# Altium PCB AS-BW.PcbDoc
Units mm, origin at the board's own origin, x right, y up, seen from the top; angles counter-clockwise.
Board outline 39.02 x 30.02 mm, 2 copper layers (Top Layer, Bottom Layer); 17 components, 20 nets, 101 pads, 184 vias.
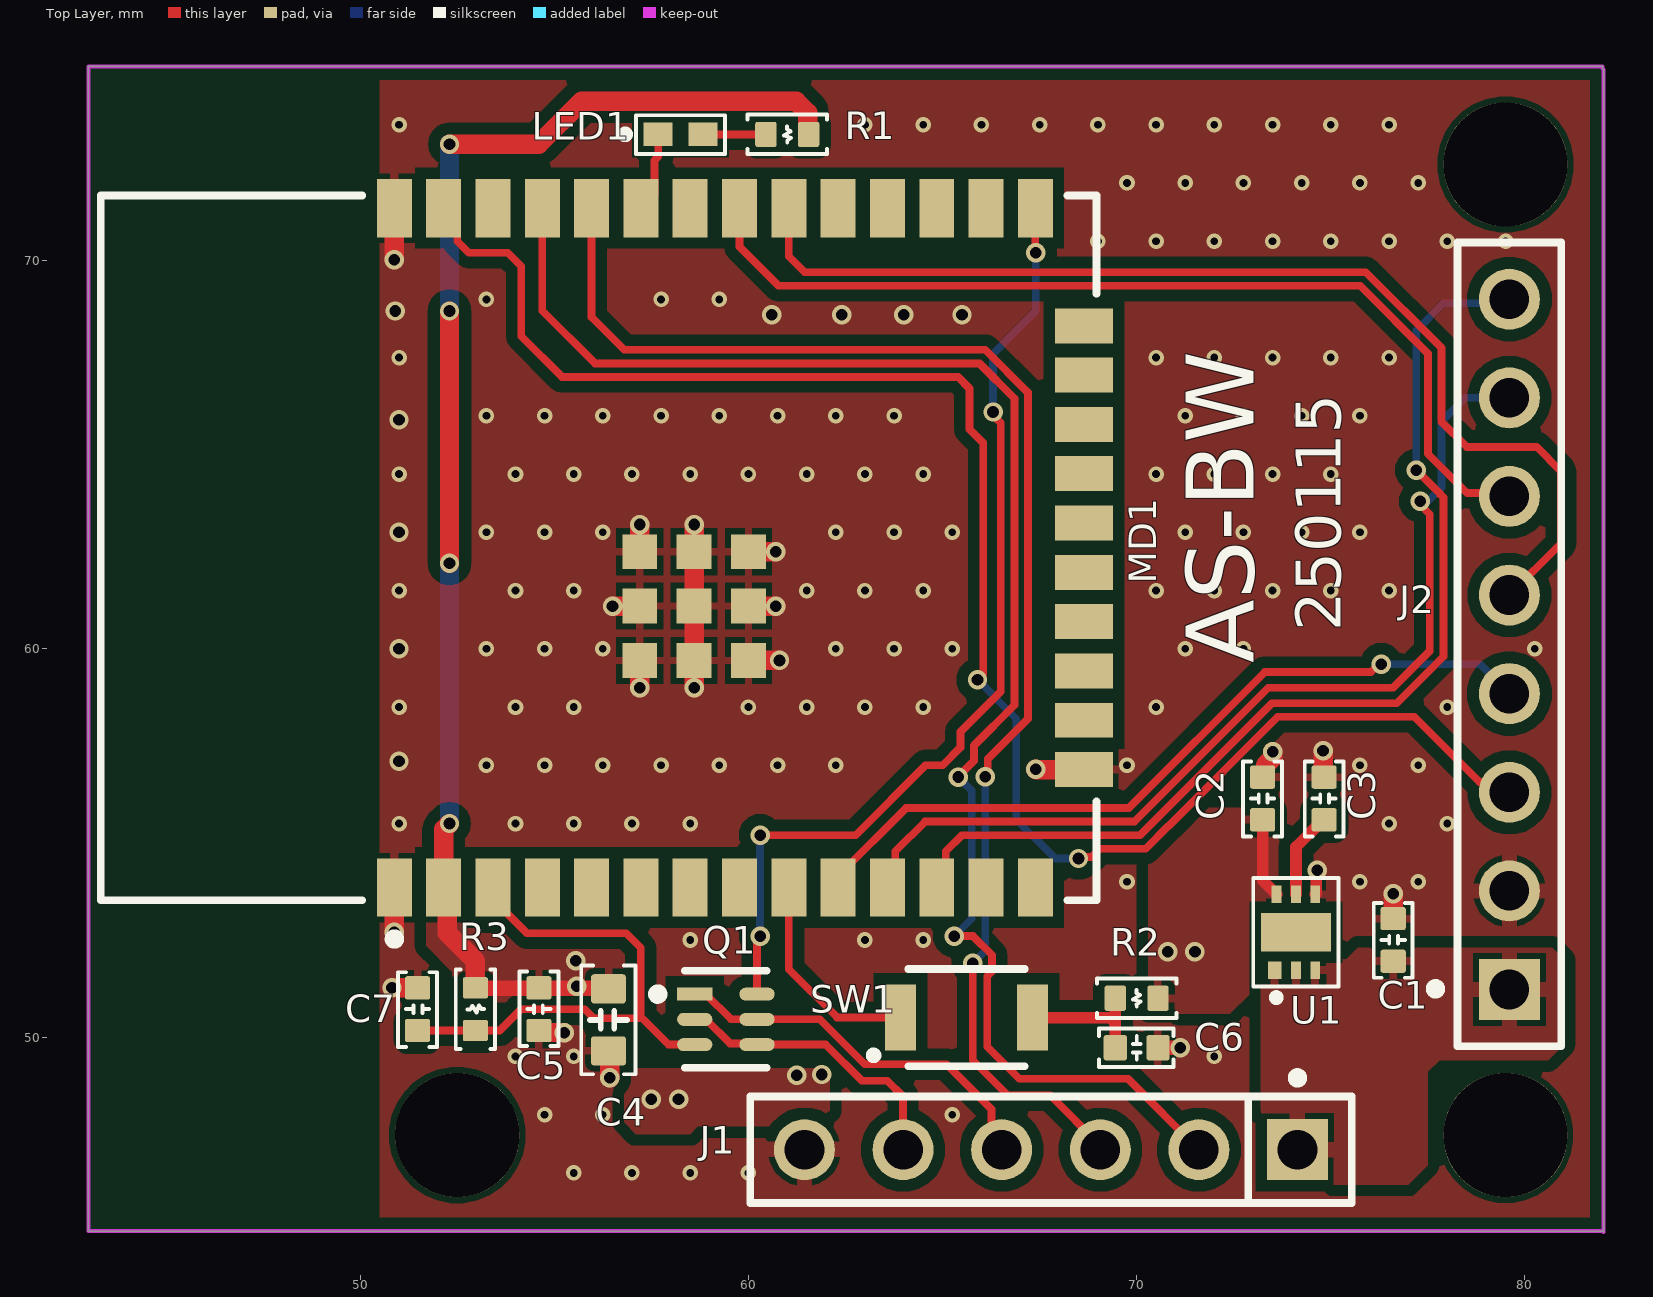
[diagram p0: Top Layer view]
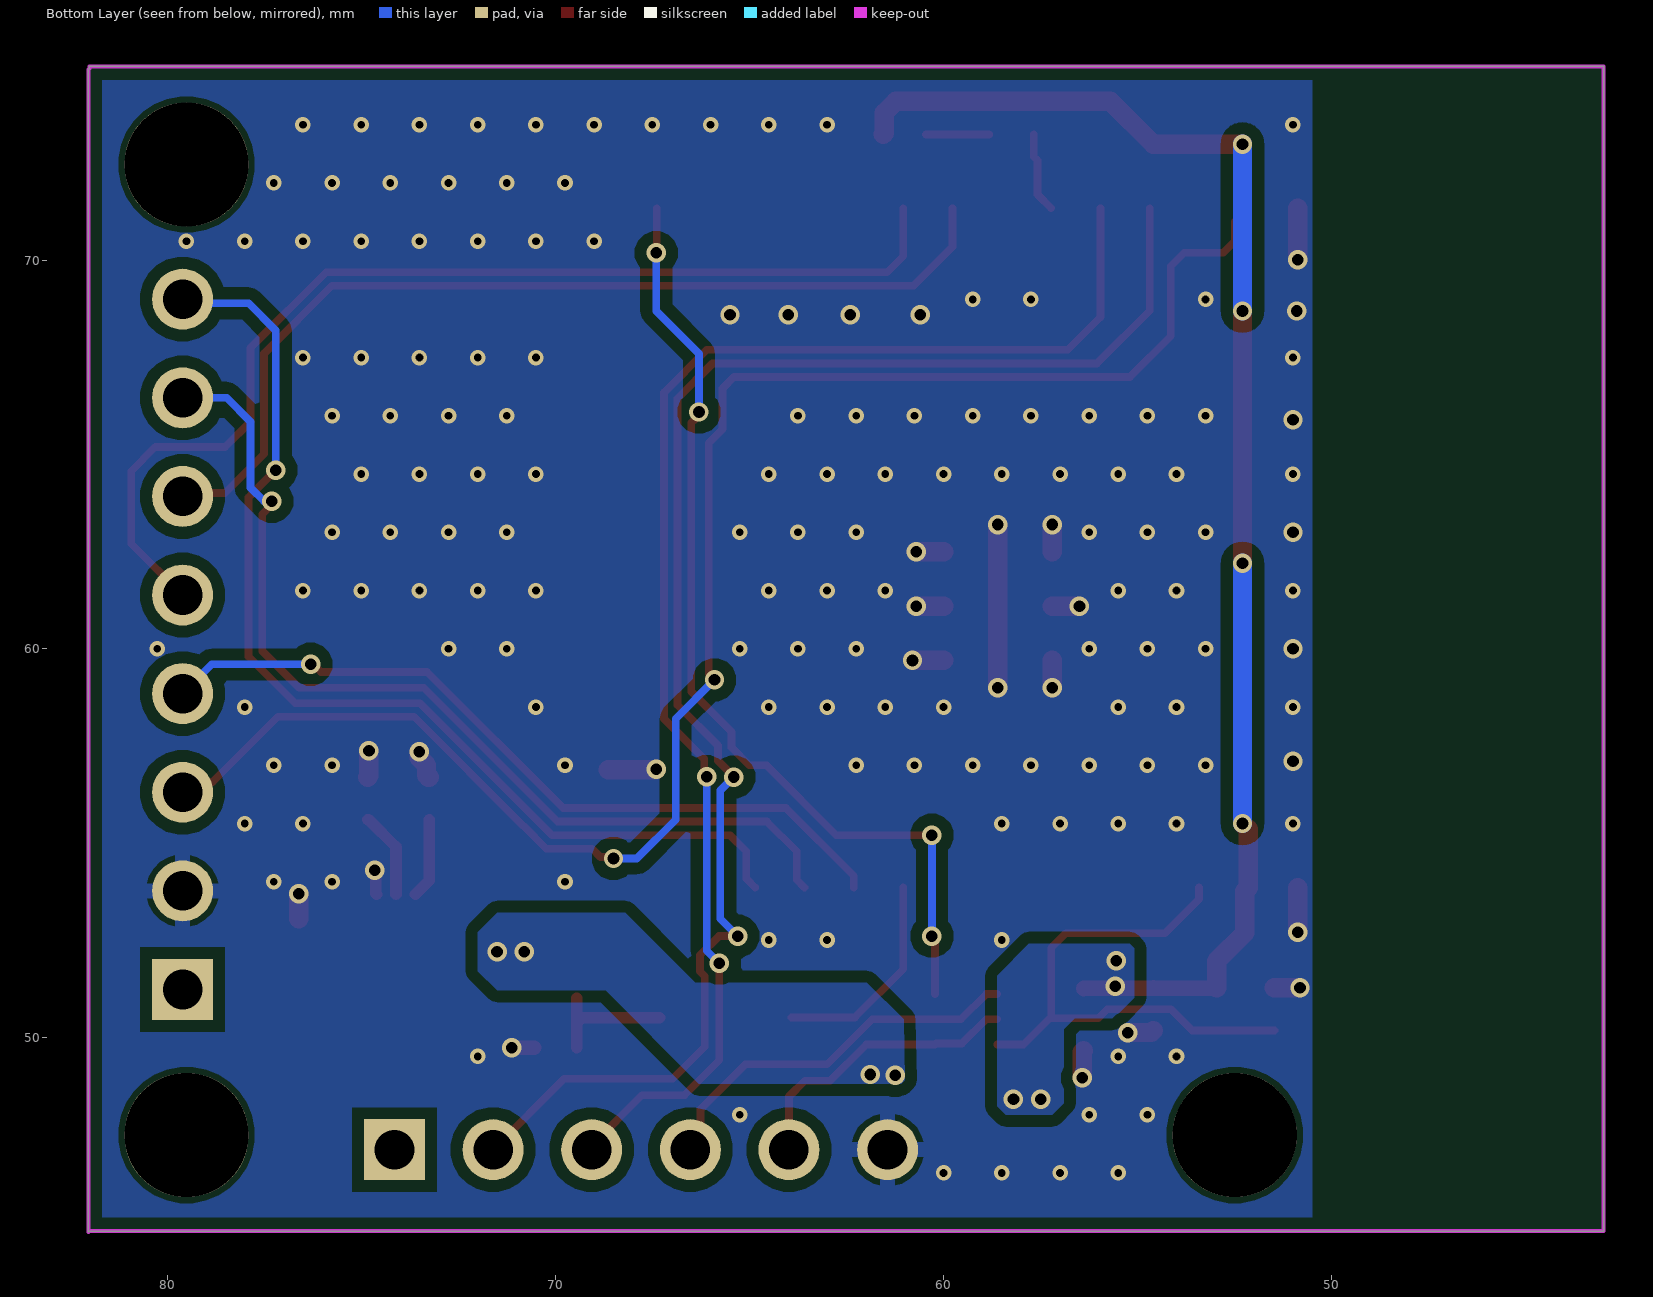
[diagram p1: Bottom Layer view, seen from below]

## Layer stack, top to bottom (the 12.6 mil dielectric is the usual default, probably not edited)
Top Solder: solder mask 0.0102, Solder Resist, Dk 3.5
Top Layer: signal copper 0.0356
Dielectric 1: dielectric 0.32, FR-4, Dk 4.8
Bottom Layer: signal copper 0.0356
Bottom Solder: solder mask 0.0102, Solder Resist, Dk 3.5

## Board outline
43,45 82,45 82.025,44.975 82.025,74.925 82,74.95 82,75 43,75

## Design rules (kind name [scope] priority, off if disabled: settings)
AssemblyTestPointUsage [All] p1 off:
AssemblyTestpoint [All] p1 off: testpointundercomponent=TRUE minsize=1.016 maxsize=2.54 preferedsize=1.524 minholesize=0 maxholesize=1.016 preferedholesize=0.813 testpointgrid=0.025 usegrid=TRUE gridtolerance=0 allowsidetop=TRUE allowsidebottom=TRUE
BoardOutlineClearance BoardOutlineClearance_1 [OnLayer('Layer 2')] p1 off: gap=0.7 ignorepadtopadclearanceinfootprint=FALSE
BoardOutlineClearance [All] p2 off: gap=0.3 ignorepadtopadclearanceinfootprint=FALSE
Clearance [All] p1: gap=0.15 ignorepadtopadclearanceinfootprint=FALSE except(0.3: Arc-Fill Arc-Poly Arc-Region Track-Fill Track-Poly Track-Region SMDPad-Fill SMDPad-Poly SMDPad-Region THPad-Fill THPad-Poly THPad-Region Via-Fill Via-Poly Via-Region Fill-Fill Fill-Poly Fill-Region Poly-Poly Poly-Region Region-Region)
ComponentClearance [All] p1 off: gap=0.254 collisioncheckmode=3 verticalgap=0.254 showdistances=FALSE
DiffPairsRouting [All] p1: maxlimit=0.254 minlimit=0.1 mostfreqgap=0.1 toplayer_minwidth=0.17 toplayer_maxwidth=0.381 toplayer_prefwidth=0.17 bottomlayer_minwidth=0.17 bottomlayer_maxwidth=0.381 bottomlayer_prefwidth=0.17 maxuncoupledlength=12.7
FabricationTestPointUsage [All] p1 off: valid=0 allowmultiple=FALSE
FabricationTestpoint [All] p1 off: side=3 testpointundercomponent=TRUE minsize=1.016 maxsize=2.54 preferedsize=1.524 minholesize=0 maxholesize=1.016 preferedholesize=0.813 testpointgrid=0.025 allowsidetop=TRUE allowsidebottom=TRUE usegrid=TRUE gridtolerance=0
Height [All] p1 off: minheight=0 maxheight=25.4 prefheight=12.7
HoleSize [All] p1 off: absolutevalues=TRUE maxlimit=2.54 minlimit=0.025 maxpercent=80.000 minpercent=20.000
HoleToHoleClearance [All] p1 off: gap=0.254 allowstackedmicrovias=TRUE
LayerPairs [All] p1 off: enforce=TRUE
MinimumSolderMaskSliver [All] p1 off: minsoldermaskwidth=0.254
NetAntennae [All] p1 off: netantennaetolerance=0
PolygonConnect [All] p1: thpad.connectstyle=Relief thpad.reliefconductorwidth=0.4 thpad.reliefentries=4 thpad.polygonreliefangle="90 Angle" thpad.airgapwidth=0.15 smdpad.connectstyle=Relief smdpad.reliefconductorwidth=0.2 smdpad.reliefentries=4 smdpad.polygonreliefangle="90 Angle" smdpad.airgapwidth=0.15 via.connectstyle=Direct via.reliefconductorwidth=0.254 via.reliefentries=4 via.polygonreliefangle="90 Angle" via.airgapwidth=0.254
RoutingVias [All] p1: holewidth=0.711 width=1.27 viastyle="Through Hole" minholewidth=0.711 minwidth=1.27 maxholewidth=0.711 maxwidth=1.27 useviatemplates=TRUE viatemplateguid#1={E85D0309-8685-4B82-8408-C28B0BDDCD2F} viatemplatename#1=v50h30m0mx0
SilkToSilkClearance [All] p1 off: silktosilkclearance=0.254
SilkToSolderMaskClearance [IsPad] p1 off: minsilkscreentomaskgap=0.254 clearancetoexposedcopper=TRUE
SolderMaskExpansion [All] p1: expansion=0.102 istentingtop=FALSE
SupplyNets "Schematic Supply Nets_3" [InNet('GND')] p1: voltage=0.000
SupplyNets "Schematic Supply Nets_2" [InNet('VCC_1V8')] p2: voltage=0.000
SupplyNets "Schematic Supply Nets_1" [InNet('VCC_5V')] p3: voltage=0.000
SupplyNets "Schematic Supply Nets" [InNet('VCC_3V3')] p4: voltage=0.000
Width [All] p1: maxlimit=3 minlimit=0.15 preferedwidth=0.15
16 further rules are at their usual default settings.

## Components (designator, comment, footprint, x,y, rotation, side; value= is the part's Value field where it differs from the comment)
C1 "Cap Semi" "CAP 0402/1005" 76.607,52.502 r270 top value=1uF
C2 "Cap Semi" "CAP 0402/1005" 73.243,56.145 r270 top value=1uF
C3 "Cap Semi" "CAP 0402/1005" 74.828,56.145 r270 top value=1uF
C4 "Cap Semi" "CAP 0603/1608" 56.395,50.443 r90 top value="22uF /1608"
C5 "Cap Semi" "CAP 0402/1005" 54.603,50.718 r90 top value=100nF
C6 "Cap Semi" "CAP 0402/1005" 70,49.725 r180 top value=100nF
C7 "Cap Semi" "CAP 0402/1005" 51.477,50.718 r270 top value=100nF
J1 "22-28-4060" FP-22-28-4060-MFG 67.792,47.098 r180 top
J2 "TSW-108-08-G-S" FP-TSW-108-08-G-S-MFG 79.6,60.115 r90 top locked
LED1 "QBLP595-IB" "LED 0402/1005 GREEN -21" 58.25,73.25 r180 top
MD1 "ESP32-WROOM-32E (4MB)" FP-ESP32-WROOM-32E_4MB-MFG 56.14,62.6 r90 top
Q1 "UMH3NTN" FP-UMT6-IPC_C 59.418,50.456 r0 top
R1 "Resistor 10k +/-1% 0805 125 mW" "RES 0402/1005" 61,73.25 r180 top value=330
R2 "Resistor 10k +/-1% 0805 125 mW" "RES 0402/1005" 70,51 r180 top value=10K
R3 "Resistor 10k +/-1% 0805 125 mW" "RES 0402/1005" 52.967,50.718 r270 top value=10K
SW1 "B3U-1000P" B3U-1000P 65.617,50.5 r180 top
U1 "VRD1833MLX" "LLP-6 / L2.0-W1.8-P0.50-BL-EP" 74.077,52.699 r0 top

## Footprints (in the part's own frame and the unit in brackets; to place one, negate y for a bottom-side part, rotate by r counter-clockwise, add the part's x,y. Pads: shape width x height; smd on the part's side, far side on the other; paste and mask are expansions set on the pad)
B3U-1000P [mm]
  rect 0.8x1.7 smd: 1(1.7,0) 2(-1.7,0)
  silkscreen extent -1.5,-1.25 2.49,1.25, body extent -2,-1.25 2,1.25, height 1.6
"CAP 0402/1005" [mm] "Chip Capacitor, 2-Leads, Body 1.02x0.51mm, IPC Medium Density"
  rrect20% 0.6x0.65 smd: 1(-0.55,0) 2(0.55,0)
  silkscreen extent -0.95,-0.5 0.97,0.5, body extent -0.5,-0.26 0.5,0.26, height 0.52
"CAP 0603/1608" [mm] "Chip Capacitor, 2-Leads, Body 1.60x0.80mm, IPC Medium Density"
  rrect20% 0.75x0.9 smd: 1(-0.8,0) 2(0.8,0)
  silkscreen extent -1.4,-0.7 1.4,0.7, body extent -0.8,-0.41 0.8,0.41, height 0.82
FP-22-28-4060-MFG [mm]
  rect 1.57x1.57 hole 1.02 paste-2539.97 mask+0: 1(-6.35,0)
  round 1.57 hole 1.02 paste-2539.97 mask+0: 2(-3.81,0) 3(-1.27,0) 4(1.27,0) 5(3.81,0) 6(6.35,0)
  silkscreen extent -7.75,-1.97 7.75,1.37, body extent -7.85,-1.47 7.85,1.47, height 0.25
FP-ESP32-WROOM-32E_4MB-MFG [mm]
  rect 1.5x0.9 smd paste+0 mask+0: 1(-8.75,5.26) 2(-8.75,3.99) 3(-8.75,2.72) 4(-8.75,1.45) 5(-8.75,0.18) 6(-8.75,-1.09) 7(-8.75,-2.36) 8(-8.75,-3.63) 9(-8.75,-4.9) 10(-8.75,-6.17) 11(-8.75,-7.44) 12(-8.75,-8.71) 13(-8.75,-9.98) 14(-8.75,-11.25) 25(8.75,-11.25) 26(8.75,-9.98) 27(8.75,-8.71) 28(8.75,-7.44) 29(8.75,-6.17) 30(8.75,-4.9) 31(8.75,-3.63) 32(8.75,-2.36) 33(8.75,-1.09) 34(8.75,0.18) 35(8.75,1.45) 36(8.75,2.72) 37(8.75,3.99) 38(8.75,5.26)
  rect 0.9x1.5 smd paste+0 mask+0: 15(-5.71,-12.5) 16(-4.44,-12.5) 17(-3.17,-12.5) 18(-1.9,-12.5) 19(-0.63,-12.5) 20(0.64,-12.5) 21(1.91,-12.5) 22(3.18,-12.5) 23(4.45,-12.5) 24(5.72,-12.5)
  rect 0.9x0.9 smd paste+0 mask+0: 39(-2.9,-2.46) 39(-2.9,-1.06) 39(-2.9,-3.86) 39(-1.5,-1.06) 39(-1.5,-3.86) 39(-1.5,-2.46) 39(-0.1,-1.06) 39(-0.1,-2.46) 39(-0.1,-3.86)
  silkscreen extent -10.2,-12.83 9.08,12.83, body extent -9.6,-13.35 9.6,12.93, height 0.25
FP-TSW-108-08-G-S-MFG [mm]
  rect 1.57x1.57 hole 1.02 paste-2539.97 mask+0: 1(-8.89,0)
  round 1.57 hole 1.02 paste-2539.97 mask+0: 2(-6.35,0) 3(-3.81,0) 4(-1.27,0) 5(1.27,0) 6(3.81,0) 7(6.35,0) 8(8.89,0)
  silkscreen extent -10.35,-1.34 10.35,2.03, body extent -10.45,-1.44 10.45,1.44, height 0.25
FP-UMT6-IPC_C [mm]
  rect 0.909x0.336 smd paste+0 mask+0: 1(-0.802,0.65)
  rrect100% 0.909x0.336 smd paste+0 mask+0: 2(-0.802,0) 3(-0.802,-0.65) 4(0.802,-0.65) 5(0.802,0) 6(0.802,0.65)
  silkscreen extent -1.88,-1.25 1.05,1.25, body extent -1.36,-1.1 1.36,1.1, height 0.25
"LED 0402/1005 GREEN -21" [mm] "Chip Diode, 2-Leads, Body 1.00x0.50mm, IPC Medium Density"
  rect 0.75x0.6 smd: 1(0.575,0) 2(-0.575,0)
  silkscreen extent -1.14,-0.49 1.47,0.51, body extent -0.5,-0.25 0.5,0.25, height 0.21
"LLP-6 / L2.0-W1.8-P0.50-BL-EP" [mm]
  rect 0.35x0.45 smd paste+0 mask+0.051: 1(-0.525,-0.975)
  rect 0.25x0.45 smd paste+0 mask+0.051: 2(0.025,-0.975) 3(0.525,-0.975) 4(0.525,0.975) 5(0.025,0.975) 6(-0.475,0.975)
  rect 1.8x1 smd paste+0 mask+0.051: 7(0.025,0)
  silkscreen extent -1.07,-1.74 1.12,1.4, body extent -0.9,-1 0.9,1, height 0.6
"RES 0402/1005" [mm] "Chip Resistor, 2-Leads, Body 1.0x0.5mm, IPC Medium Density"
  rrect20% 0.55x0.65 smd: 1(-0.55,0) 2(0.55,0)
  silkscreen extent -1.02,-0.51 1.02,0.51, body extent -0.5,-0.25 0.5,0.25, height 0.35

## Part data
C1 C2 C3 C4 C5 C6 C7: "Capacitor (Semiconductor SIM Model)"
J1: library part CMP-04776-000763-1, "CONN HEADER VERT 6POS 2.54MM", Color=Black, Contact Resistance=20mR, Current Rating=4A, Max Operating Temperature=75°C, Max Voltage Rating (AC)=250V, Max Voltage Rating (DC)=250.25kV, Min Operating Temperature=0°C, Package Quantity=1
J2: library part CMP-02766-000001-1, "CONN HEADER VERT 8POS 2.54MM", Manufacturer=Samtec, Temperature="-55°C to +125°C", Temperature Range High=+125°C, Temperature Range Low=-55°C
LED1: "Chip LED 0402, Blue, 0.02 A, 3.1 to 3.7 V, -40 to 80 degC, 2-Pin SMD, RoHS, Tape and Reel", Case/Package=0402, Colour=Blue
MD1: library part CMP-194065-000026-1, "RX TXRX MOD WIFI TRACE ANT SMD"
Q1: library part CMP-08979-000010-1, "TRANS 2NPN PREBIAS 0.15W UMT6", Case/Package=SOT-363, Collector Base Voltage (VCBO)=50V, Collector-emitter Voltage-Max=300mV, Continuous Collector Current=100mA, Emitter Base Voltage (VEBO)=5V, Max Operating Temperature=150°C, Max Power Dissipation=150mW, Min Operating Temperature=-55°C, Package Quantity=1, Transition Frequency=250MHz
R1 R2 R3: "Chip Resistor, 10 KOhm, +/- 1%, 125 mW, -55 to 155 degC, 0805 (2012 Metric)", Case/Package=0805, Max Operating Temperature=155°C, Min Operating Temperature=-55°C, Power=125mW, Tolerance=1%, Voltage Rating=150V
SW1: "Tactile Switch, SPST-NO, 0.05 A, 12 V, -25 to 70 degC, 2-Pin SMD, RoHS, Tape and Reel", Case/Package=B3U-1000, Contact Current Rating=50mA, IP Rating=IP40, Manufacturer="Omron Electronic Components", Max Contact Resistance=100mohm, Max Operating Temperature=70°C, Max Voltage Rating (DC)=12V, Min Operating Temperature=-25°C, Operating Force=153gf, Package Description="2-Pin Surface Mount Device, Body 3 x 2.5 mm", Package Quantity=3500, Resistance=0.1Ohm

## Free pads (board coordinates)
  round 3.2 hole 3.2: 0(52.5,47.475) 0(79.5,47.475) 0(79.5,72.475)

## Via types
v1: diameter 0.4, hole 0.2, Top Layer to Bottom Layer, tented both sides, 131 vias
v2: diameter 0.5, hole 0.3, Top Layer to Bottom Layer, tented both sides, 53 vias

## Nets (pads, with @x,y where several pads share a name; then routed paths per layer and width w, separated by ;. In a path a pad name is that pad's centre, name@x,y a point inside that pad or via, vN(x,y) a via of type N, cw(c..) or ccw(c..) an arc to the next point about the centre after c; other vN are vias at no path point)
GND: C1.1 C2.1 C3.1 C4.1 C5.1 C6.1 C7.1 J1.6 J2.2 MD1.1 MD1.15 MD1.38 MD1.39 U1.4 | length 17.6
  Top Layer w0.3: U1.4 74.627,53.699 74.627,54.273 v2(74.652,54.298)
  Top Layer w0.381: C6.1 v2(71.125,49.725)
  Top Layer w0.5: v2(50.818,51.268) C7.1 ; v2(50.88,52.695) MD1.1 ; v2(50.88,70.02) MD1.38 ; C5.1 54.653,50.118 55.249,50.118 v2(55.253,50.114) ; C4.1 56.425,49.612 v2(56.425,48.95) ; v2(56.5,61.1) MD1.39@57.2,61.1 ; v2(57.2,59) MD1.39@57.2,59.7 ; MD1.39@57.2,62.5 v2(57.2,63.2) ; v2(58.6,59) 58.6,59.7 58.6,61.1 58.6,62.5 v2(58.6,63.2) ; MD1.39@60,59.7 v2(60.8,59.7) ; MD1.39@60,61.1 v2(60.7,61.1) ; MD1.39@60,62.5 v2(60.7,62.5) ; v2(67.4,56.9) 67.41,56.89 MD1.15 ; C2.1 73.268,56.695 73.318,56.745 73.318,57.007 73.5,57.189 v2(73.5,57.345) ; v2(74.8,57.375) 74.8,56.723 C3.1 ; C1.1 v2(76.607,53.693)
  other v1: 55.5,46.5 57,46.5 58.5,46.5 60,46.5 54.75,48 56.25,48 65.25,48 54,49.5 55.5,49.5 72,49.5 58.5,52.5 63,52.5 64.5,52.5 69.75,54 75.75,54 77.25,54 51,55.5 54,55.5 55.5,55.5 57,55.5 58.5,55.5 76.5,55.5 78,55.5 53.25,57 54.75,57 56.25,57 57.75,57 59.25,57 60.75,57 62.25,57 69.75,57 75.75,57 77.25,57 51,58.5 54,58.5 55.5,58.5 60,58.5 61.5,58.5 63,58.5 64.5,58.5 70.5,58.5 78,58.5 53.25,60 54.75,60 56.25,60 62.25,60 63.75,60 65.25,60 71.25,60 72.75,60 80.25,60 51,61.5 54,61.5 55.5,61.5 61.5,61.5 63,61.5 64.5,61.5 70.5,61.5 72,61.5 73.5,61.5 75,61.5 76.5,61.5 53.25,63 54.75,63 56.25,63 62.25,63 63.75,63 65.25,63 71.25,63 72.75,63 74.25,63 75.75,63 51,64.5 54,64.5 55.5,64.5 57,64.5 58.5,64.5 60,64.5 61.5,64.5 63,64.5 64.5,64.5 70.5,64.5 72,64.5 73.5,64.5 75,64.5 53.25,66 54.75,66 56.25,66 57.75,66 59.25,66 60.75,66 62.25,66 63.75,66 71.25,66 72.75,66 74.25,66 75.75,66 51,67.5 70.5,67.5 72,67.5 73.5,67.5 75,67.5 76.5,67.5 53.25,69 57.75,69 59.25,69 69,70.5 70.5,70.5 72,70.5 73.5,70.5 75,70.5 76.5,70.5 78,70.5 79.5,70.5 69.75,72 71.25,72 72.75,72 74.25,72 75.75,72 77.25,72 51,73.5 63,73.5 64.5,73.5 66,73.5 67.5,73.5 69,73.5 70.5,73.5 72,73.5 73.5,73.5 75,73.5 76.5,73.5
  other v2: 51,57.1 51,60 51,63 51,65.9 60.6,68.6 62.4,68.6 64,68.6 65.5,68.6 50.9,68.7
NetC6_2: C6.2 R2.2 SW1.2 | length 3.5
  Top Layer w0.3: SW1.2 69.312,50.5 69.45,50.363 ; C6.2 69.45,50.363 ; R2.2 69.45,50.363
NetC7_2: C7.2 MD1.3 Q1.3 R3.2 | length 14.2
  Top Layer w0.2: C7.2 R3.2 53.593,50.168 54.143,50.718 55.785,50.718 56.019,50.484 57.266,50.484 ; MD1.3 53.42,53.55 54.295,52.675 56.85,52.675 57.225,52.3 57.225,50.525 57.266,50.484 ; Q1.3 57.944,49.806 57.266,50.484
NetJ1_2: J1.2 MD1.35 | length 40.7
  Top Layer w0.2: MD1.35 54.69,68.71 56.05,67.35 65.95,67.35 66.85,66.45 66.85,58.55 65.811,57.511 65.811,57.118 65.404,56.711 v2(65.404,56.696) ; v2(65.3,52.6) 65.782,52.6 66.275,52.107 66.275,51.693 66.15,51.568 66.15,49.75 66.975,48.925 69.775,48.925 J1.2
  Bottom Layer w0.2: v2(65.3,52.6) 65.75,53.05 65.75,56.35 v2(65.404,56.696)
NetJ1_3: J1.3 MD1.34 | length 36.9
  Top Layer w0.2: MD1.34 55.96,68.54 56.8,67.7 66.1,67.7 67.2,66.6 67.2,58.2 66.161,57.161 66.161,56.761 v2(66.104,56.704) ; v2(65.775,51.9) 65.775,49.4 66.675,48.5 67.77,48.5 69.062,47.208 J1.3
  Bottom Layer w0.2: v2(65.775,51.9) 66.1,52.225 66.1,56.7 v2(66.104,56.704)
NetJ1_4: J1.4 Q1.1 Q1.5 | length 10
  Top Layer w0.2: Q1.1 58.903,51.106 59.553,50.456 Q1.5 61.839,50.456 62.995,49.3 65.1,49.3 66.26,48.14 66.26,47.36 J1.4
NetJ1_5: J1.5 Q1.2 Q1.4 | length 7.6
  Top Layer w0.2: Q1.2 58.903,50.456 59.527,49.832 60.194,49.832 Q1.4 61.994,49.806 62.925,48.875 63.575,48.875 63.982,48.468 J1.5
NetJ2_3: J2.3 MD1.37 | length 44
  Top Layer w0.2: MD1.37 52.5,71 52.5,70.5 52.8,70.2 53.8,70.2 54.15,69.85 54.15,68.05 55.2,67 65.4,67 65.694,66.706 65.694,65.656 66.05,65.3 66.05,59.35 v2(65.9,59.2) ; v2(68.5,54.6) 68.539,54.639 68.839,54.639 69.05,54.85 70.231,54.85 70.817,55.437 70.821,55.437 73.635,58.25 77.15,58.25 78.833,56.567 79.338,56.567 J2.3
  Bottom Layer w0.2: v2(65.9,59.2) 66.9,58.2 66.9,55.6 67.9,54.6 v2(68.5,54.6)
NetJ2_4: J2.4 MD1.10 | length 20.2
  Top Layer w0.2: MD1.10 62.31,54.15 64.06,55.9 69.796,55.9 73.296,59.4 76.033,59.4 76.233,59.6 v2(76.3,59.6)
  Bottom Layer w0.2: v2(76.3,59.6) 78.845,59.6 J2.4
NetJ2_5: J2.5 MD1.30 | length 28.3
  Top Layer w0.2: MD1.30 61.04,70.11 61.45,69.7 75.9,69.7 77.85,67.75 77.85,65.85 78.5,65.2 80.3,65.2 80.925,64.575 80.925,62.71 J2.5
NetJ2_6: J2.6 MD1.31 | length 25
  Top Layer w0.2: MD1.31 59.77,70.355 60.775,69.35 75.755,69.35 77.5,67.605 77.5,65.025 78.515,64.01 79.515,64.01 J2.6
NetJ2_7: J2.7 MD1.11 | length 25.3
  Top Layer w0.2: MD1.11 63.783,54.053 63.783,54.783 64.55,55.55 69.941,55.55 73.388,58.997 76.603,58.997 77.55,59.945 77.55,63.469 77.3,63.719 v2(77.3,63.8)
  Bottom Layer w0.2: v2(77.3,63.8) 77.5,63.8 77.85,64.15 77.85,65.85 78.465,66.465 J2.7
NetJ2_8: J2.8 MD1.12 | length 27.4
  Top Layer w0.2: MD1.12 65.083,54.083 65.083,54.783 65.5,55.2 70.086,55.2 73.486,58.6 76.7,58.6 77.9,59.8 77.9,63.9 77.8,64 77.8,64.007 77.207,64.6 v2(77.2,64.6)
  Bottom Layer w0.2: v2(77.2,64.6) 77.2,68.2 77.9,68.9 79.495,68.9 J2.8
NetLED1_1: LED1.1 MD1.33 | length 2.1
  Top Layer w0.2: MD1.33 57.58,71.7 57.58,72.58 57.675,72.675 LED1.1
NetLED1_2: LED1.2 R1.2 | length 1.6
  Top Layer w0.2: LED1.2 R1.2
NetMD1_9: MD1.9 SW1.1 | length 5.5
  Top Layer w0.2: MD1.9 61.04,51.75 62.284,50.506 62.815,50.506 62.821,50.5 SW1.1
NetMD1_25: MD1.25 Q1.6 | length 25.1
  Top Layer w0.2: Q1.6 60.22,52.52 v2(60.3,52.6) ; v2(60.3,55.2) 62.762,55.2 64.562,57 65,57 65.461,57.461 65.461,57.861 66.5,58.9 66.5,65.7 66.5,65.819 v2@66.4,65.919 ; v2(66.3,66.1) 66.381,66.019 66.4,66.019 v2@66.4,66.1 ; MD1.25 67.39,70.21 v2(67.4,70.2)
  Bottom Layer w0.2: v2(60.3,52.6) 60.3,55 60.317,55.017 60.317,55.183 v2(60.3,55.2) ; v2(66.3,66.1) 66.3,67.6 67.4,68.7 v2(67.4,70.2)
VCC_1V8: C3.2 U1.5 | length 2.2
  Top Layer w0.3: U1.5 74.102,54.895 74.803,55.595 C3.2
VCC_3V3: C2.2 C4.2 C5.2 MD1.2 R1.1 R2.1 R3.1 U1.6 | length 38.1
  Top Layer w0.3: C2.2 73.243,54.033 U1.6
  Top Layer w0.4: R3.1 53.08,51.268 53.092,51.255 54.59,51.255 C5.2 ; C5.2@54.603,51.255 55.5,51.255 55.552,51.308 v2(55.579,51.308) ; v2@55.527,51.255 56.382,51.255 C4.2
  Top Layer w0.5: v2(52.3,55.5) 52.15,55.35 MD1.2 52.243,53.757 52.243,52.682 52.967,51.958 R3.1 ; v2(52.3,62.2) v2(52.3,68.7) ; v2(52.3,73) 54.6,73 55.7,74.1 61.232,74.1 61.525,73.807 61.525,73.275 R1.1
  Bottom Layer w0.5: v2(52.3,55.5) v2(52.3,62.2) ; v2(52.3,68.7) v2(52.3,73)
  other v2: 57.5,48.4 58.2,48.4 61.247,49.013 61.892,49.035 55.556,51.962 70.8,52.2 71.5,52.2
VCC_5V: C1.2 J1.1 J2.1 U1.1 U1.2 U1.3
pads on no net: MD1.4 MD1.5 MD1.6 MD1.7 MD1.8 MD1.13 MD1.14 MD1.16 MD1.17 MD1.18 MD1.19 MD1.20 MD1.21 MD1.22 MD1.23 MD1.24 MD1.26 MD1.27 MD1.28 MD1.29 MD1.32 MD1.36 U1.7

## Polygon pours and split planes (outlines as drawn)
GND on Top Layer "GND_L01_P006" (solid, pour order 6): 43,45 82,45 82.025,44.975 82.025,74.925 82,74.95 82,75 43,75
VCC_3V3 on Top Layer "NONET_L03_P-001" (solid, pour order 4): 57.031,49.201 62.099,49.201 62.099,47.7 58.7,47.7 58.5,47.5 57.1,47.5 56.8,47.8 56.8,48.97
VCC_3V3 on Top Layer "NONET_L03_P-001" (solid, pour order 2): 51.7,54.575 51.7,52.35 52.375,51.675 52.375,51.075 52.55,50.9 56.825,50.9 56.95,51.025 56.95,52.575 56.85,52.675 53.125,52.675 52.625,53.175 52.625,54.475 52.525,54.575
VCC_3V3 on Top Layer "NONET_L03_P-001" (solid, pour order 1): 70.3,55 71.2,55.9 73.5,55.9 73.7,55.7 73.7,53.5 73.1,53.5 72.9,53.3 72.9,51.1 72.4,50.6 70.4,50.6 70.3,50.7
VCC_5V on Top Layer "NONET_L03_P-001" (solid, pour order 0): 73.2,52 75.4,52 75.7,52.3 80.7,52.3 81,52 81,49.8 80.6,49.4 77.8,49.4 77.5,49.1 77.5,46.7 77,46.2 73.4,46.2 73.2,46.4 73.2,47.6
GND on Bottom Layer "GND_L02_P007" (solid, pour order 7): 43,45 82,45 82.025,44.975 82.025,74.925 82,74.95 82,75 43,75
VCC_3V3 on Bottom Layer "NONET_L03_P-001" (solid, pour order 5): 60.997,48.8 66.3,48.8 68.7,51.2 71.5,51.2 72,51.7 72,52.7 71.5,53.2 68.2,53.2 66.4,51.4 61.973,51.4 61.029,50.456
VCC_3V3 on Bottom Layer "NONET_L03_P-001" (solid, pour order 3): 57.8,52.4 58.616,51.584 58.616,48.216 58.4,48 57.2,48 56.9,48.3 56.9,50.2 56.616,50.484 55.616,50.484 55.082,51.018 55.082,52.282 55.2,52.4

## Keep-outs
Keep-Out Layer:
  lines w0.1: 82,74.95 82.025,74.925 82.025,44.975 82,45 43,45 43,75 82,75

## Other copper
Multi-Layer:
  pour cut-out: 43,75 50.5,75 50.5,45 43,45

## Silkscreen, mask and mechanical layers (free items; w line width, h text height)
Top Overlay:
  text "250115" at 75.647,60.448 h2 r90
  text "AS-BW" at 73.591,59.632 h3 r90
Dimensions:
  text "Layer : 4L" at 87.125,56.233 h3
  text "Thickiness : 1.0mm" at 86.925,52.706 h3

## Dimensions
82.025,44.975 to 82,74.95 on Dimensions
43,75 to 82.025,74.925 on Dimensions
